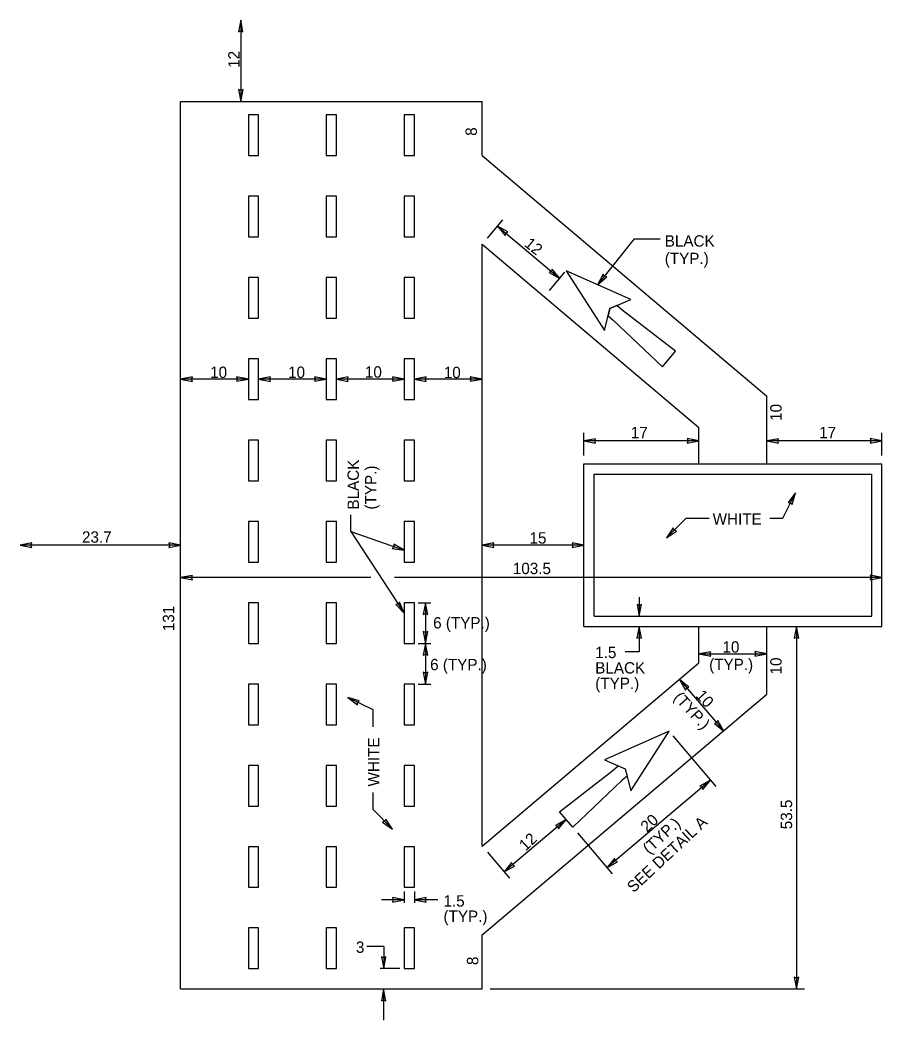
# Model space of a CAD drawing. Extents: x 319706 to 320019, y 1621790 to 1621976.
# Drawn here: x 319837.4 to 319943.4, y 1621853.1 to 1621976.1 of the extents above; entities that cross this region are included whole.
import ezdxf

# ---------------------------------------------------------------- set-up
doc = ezdxf.new("R2010")
doc.units = 0
for name, color, linetype in [('1', 7, 'Continuous'), ('40', 7, 'Continuous'), ('48', 7, 'Continuous'), ('52', 7, 'Continuous')]:
    doc.layers.add(name, color=color, linetype=linetype)

msp = doc.modelspace()

# ---------------------------------------------------------------- linework, layer by layer
at = {"layer": '1'}
for p, q in [((319857.17, 1621966.12), (319894.25, 1621966.12)), ((319857.17, 1621856.96), (319857.17, 1621966.12)), ((319894.25, 1621959.46), (319894.25, 1621966.12)), ((319894.25, 1621959.46), (319929.25, 1621929.87)), ((319894.25, 1621948.55), (319920.91, 1621926.01)), ((319894.25, 1621874.54), (319894.25, 1621948.55)), ((319929.25, 1621921.54), (319929.25, 1621929.87)), ((319920.91, 1621921.54), (319920.91, 1621926.01)), ((319906.75, 1621901.54), (319906.75, 1621921.54)), ((319906.75, 1621921.54), (319943.41, 1621921.54)), ((319943.41, 1621901.54), (319943.41, 1621921.54)), ((319908, 1621920.29), (319942.16, 1621920.29)), ((319908, 1621902.79), (319908, 1621920.29)), ((319942.16, 1621902.79), (319942.16, 1621920.29)), ((319908, 1621902.79), (319942.16, 1621902.79)), ((319906.75, 1621901.54), (319943.41, 1621901.54)), ((319920.91, 1621897.08), (319920.91, 1621901.54)), ((319929.25, 1621893.21), (319929.25, 1621901.54)), ((319894.25, 1621874.54), (319920.91, 1621897.08)), ((319894.25, 1621863.62), (319929.25, 1621893.21)), ((319894.25, 1621856.96), (319894.25, 1621863.62)), ((319857.17, 1621856.96), (319894.25, 1621856.96))]:
    msp.add_line(p, q, dxfattribs=at)
at = {"layer": '40'}
for p, q in [((319866.75, 1621964.46), (319865.5, 1621964.46)), ((319865.5, 1621964.46), (319865.5, 1621959.46)), ((319866.75, 1621959.46), (319866.75, 1621964.46)), ((319876.33, 1621964.46), (319875.08, 1621964.46)), ((319875.08, 1621964.46), (319875.08, 1621959.46)), ((319876.33, 1621959.46), (319876.33, 1621964.46)), ((319885.91, 1621964.46), (319884.66, 1621964.46)), ((319884.66, 1621964.46), (319884.66, 1621959.46)), ((319885.91, 1621959.46), (319885.91, 1621964.46)), ((319865.5, 1621959.46), (319866.75, 1621959.46)), ((319875.08, 1621959.46), (319876.33, 1621959.46)), ((319884.66, 1621959.46), (319885.91, 1621959.46)), ((319866.75, 1621954.46), (319865.5, 1621954.46)), ((319865.5, 1621954.46), (319865.5, 1621949.46)), ((319866.75, 1621949.46), (319866.75, 1621954.46)), ((319876.33, 1621954.46), (319875.08, 1621954.46)), ((319875.08, 1621954.46), (319875.08, 1621949.46)), ((319876.33, 1621949.46), (319876.33, 1621954.46)), ((319885.91, 1621954.46), (319884.66, 1621954.46)), ((319884.66, 1621954.46), (319884.66, 1621949.46)), ((319885.91, 1621949.46), (319885.91, 1621954.46)), ((319865.5, 1621949.46), (319866.75, 1621949.46)), ((319875.08, 1621949.46), (319876.33, 1621949.46)), ((319884.66, 1621949.46), (319885.91, 1621949.46)), ((319904.57, 1621945.27), (319909.27, 1621937.95)), ((319912.53, 1621941.75), (319904.57, 1621945.27)), ((319866.75, 1621944.46), (319865.5, 1621944.46)), ((319865.5, 1621944.46), (319865.5, 1621939.46)), ((319866.75, 1621939.46), (319866.75, 1621944.46)), ((319876.33, 1621944.46), (319875.08, 1621944.46)), ((319875.08, 1621944.46), (319875.08, 1621939.46)), ((319876.33, 1621939.46), (319876.33, 1621944.46)), ((319885.91, 1621944.46), (319884.66, 1621944.46)), ((319884.66, 1621944.46), (319884.66, 1621939.46)), ((319885.91, 1621939.46), (319885.91, 1621944.46)), ((319909.95, 1621940.66), (319912.53, 1621941.75)), ((319909.27, 1621937.95), (319909.95, 1621940.66)), ((319909.95, 1621940.66), (319909.73, 1621939.76)), ((319910.81, 1621941.03), (319909.95, 1621940.66)), ((319911.44, 1621940.48), (319910.81, 1621941.03)), ((319918.04, 1621935.38), (319911.44, 1621940.48)), ((319865.5, 1621939.46), (319866.75, 1621939.46)), ((319875.08, 1621939.46), (319876.33, 1621939.46)), ((319884.66, 1621939.46), (319885.91, 1621939.46)), ((319909.73, 1621939.76), (319910.36, 1621939.22)), ((319910.36, 1621939.22), (319916.41, 1621933.48)), ((319916.41, 1621933.48), (319918.04, 1621935.38)), ((319866.75, 1621934.46), (319865.5, 1621934.46)), ((319865.5, 1621934.46), (319865.5, 1621929.46)), ((319866.75, 1621929.46), (319866.75, 1621934.46)), ((319876.33, 1621934.46), (319875.08, 1621934.46)), ((319875.08, 1621934.46), (319875.08, 1621929.46)), ((319876.33, 1621929.46), (319876.33, 1621934.46)), ((319885.91, 1621934.46), (319884.66, 1621934.46)), ((319884.66, 1621934.46), (319884.66, 1621929.46)), ((319885.91, 1621929.46), (319885.91, 1621934.46)), ((319865.5, 1621929.46), (319866.75, 1621929.46)), ((319875.08, 1621929.46), (319876.33, 1621929.46)), ((319884.66, 1621929.46), (319885.91, 1621929.46)), ((319866.75, 1621924.46), (319865.5, 1621924.46)), ((319865.5, 1621924.46), (319865.5, 1621919.46)), ((319866.75, 1621919.46), (319866.75, 1621924.46)), ((319876.33, 1621924.46), (319875.08, 1621924.46)), ((319875.08, 1621924.46), (319875.08, 1621919.46)), ((319876.33, 1621919.46), (319876.33, 1621924.46)), ((319885.91, 1621924.46), (319884.66, 1621924.46)), ((319884.66, 1621924.46), (319884.66, 1621919.46)), ((319885.91, 1621919.46), (319885.91, 1621924.46)), ((319865.5, 1621919.46), (319866.75, 1621919.46)), ((319875.08, 1621919.46), (319876.33, 1621919.46)), ((319884.66, 1621919.46), (319885.91, 1621919.46)), ((319866.75, 1621914.46), (319865.5, 1621914.46)), ((319865.5, 1621914.46), (319865.5, 1621909.46)), ((319866.75, 1621909.46), (319866.75, 1621914.46)), ((319876.33, 1621914.46), (319875.08, 1621914.46)), ((319875.08, 1621914.46), (319875.08, 1621909.46)), ((319876.33, 1621909.46), (319876.33, 1621914.46)), ((319885.91, 1621914.46), (319884.66, 1621914.46)), ((319884.66, 1621914.46), (319884.66, 1621909.46)), ((319885.91, 1621909.46), (319885.91, 1621914.46)), ((319865.5, 1621909.46), (319866.75, 1621909.46)), ((319875.08, 1621909.46), (319876.33, 1621909.46)), ((319884.66, 1621909.46), (319885.91, 1621909.46)), ((319866.75, 1621904.46), (319865.5, 1621904.46)), ((319865.5, 1621904.46), (319865.5, 1621899.46)), ((319866.75, 1621899.46), (319866.75, 1621904.46)), ((319876.33, 1621904.46), (319875.08, 1621904.46)), ((319875.08, 1621904.46), (319875.08, 1621899.46)), ((319876.33, 1621899.46), (319876.33, 1621904.46)), ((319885.91, 1621904.46), (319884.66, 1621904.46)), ((319884.66, 1621904.46), (319884.66, 1621899.46)), ((319885.91, 1621899.46), (319885.91, 1621904.46)), ((319865.5, 1621899.46), (319866.75, 1621899.46)), ((319875.08, 1621899.46), (319876.33, 1621899.46)), ((319884.66, 1621899.46), (319885.91, 1621899.46)), ((319866.75, 1621894.46), (319865.5, 1621894.46)), ((319865.5, 1621894.46), (319865.5, 1621889.46)), ((319866.75, 1621889.46), (319866.75, 1621894.46)), ((319876.33, 1621894.46), (319875.08, 1621894.46)), ((319875.08, 1621894.46), (319875.08, 1621889.46)), ((319876.33, 1621889.46), (319876.33, 1621894.46)), ((319885.91, 1621894.46), (319884.66, 1621894.46)), ((319884.66, 1621894.46), (319884.66, 1621889.46)), ((319885.91, 1621889.46), (319885.91, 1621894.46)), ((319865.5, 1621889.46), (319866.75, 1621889.46)), ((319875.08, 1621889.46), (319876.33, 1621889.46)), ((319884.66, 1621889.46), (319885.91, 1621889.46)), ((319917.23, 1621888.66), (319909.27, 1621885.13)), ((319912.53, 1621881.33), (319917.23, 1621888.66)), ((319909.27, 1621885.13), (319911.85, 1621884.05)), ((319866.75, 1621884.46), (319865.5, 1621884.46)), ((319865.5, 1621884.46), (319865.5, 1621879.46)), ((319866.75, 1621879.46), (319866.75, 1621884.46)), ((319876.33, 1621884.46), (319875.08, 1621884.46)), ((319875.08, 1621884.46), (319875.08, 1621879.46)), ((319876.33, 1621879.46), (319876.33, 1621884.46)), ((319885.91, 1621884.46), (319884.66, 1621884.46)), ((319884.66, 1621884.46), (319884.66, 1621879.46)), ((319885.91, 1621879.46), (319885.91, 1621884.46)), ((319903.76, 1621878.76), (319910.36, 1621883.87)), ((319910.36, 1621883.87), (319910.99, 1621884.41)), ((319910.99, 1621884.41), (319911.85, 1621884.05)), ((319911.85, 1621884.05), (319912.08, 1621883.14)), ((319911.85, 1621884.05), (319912.53, 1621881.33)), ((319911.44, 1621882.6), (319905.39, 1621876.86)), ((319912.08, 1621883.14), (319911.44, 1621882.6)), ((319865.5, 1621879.46), (319866.75, 1621879.46)), ((319875.08, 1621879.46), (319876.33, 1621879.46)), ((319884.66, 1621879.46), (319885.91, 1621879.46)), ((319905.39, 1621876.86), (319903.76, 1621878.76)), ((319866.75, 1621874.46), (319865.5, 1621874.46)), ((319865.5, 1621874.46), (319865.5, 1621869.46)), ((319866.75, 1621869.46), (319866.75, 1621874.46)), ((319876.33, 1621874.46), (319875.08, 1621874.46)), ((319875.08, 1621874.46), (319875.08, 1621869.46)), ((319876.33, 1621869.46), (319876.33, 1621874.46)), ((319885.91, 1621874.46), (319884.66, 1621874.46)), ((319884.66, 1621874.46), (319884.66, 1621869.46)), ((319885.91, 1621869.46), (319885.91, 1621874.46)), ((319865.5, 1621869.46), (319866.75, 1621869.46)), ((319875.08, 1621869.46), (319876.33, 1621869.46)), ((319884.66, 1621869.46), (319885.91, 1621869.46)), ((319866.75, 1621864.46), (319865.5, 1621864.46)), ((319865.5, 1621864.46), (319865.5, 1621859.46)), ((319866.75, 1621859.46), (319866.75, 1621864.46)), ((319876.33, 1621864.46), (319875.08, 1621864.46)), ((319875.08, 1621864.46), (319875.08, 1621859.46)), ((319876.33, 1621859.46), (319876.33, 1621864.46)), ((319885.91, 1621864.46), (319884.66, 1621864.46)), ((319884.66, 1621864.46), (319884.66, 1621859.46)), ((319885.91, 1621859.46), (319885.91, 1621864.46)), ((319865.5, 1621859.46), (319866.75, 1621859.46)), ((319875.08, 1621859.46), (319876.33, 1621859.46)), ((319884.66, 1621859.46), (319885.91, 1621859.46))]:
    msp.add_line(p, q, dxfattribs=at)
at = {"layer": '48'}
for p, q in [((319864.56, 1621976.12), (319864.56, 1621966.12)), ((319894.89, 1621949.31), (319896.79, 1621951.55)), ((319896.14, 1621950.79), (319903.78, 1621944.34)), ((319912.93, 1621949.23), (319908.44, 1621943.56)), ((319912.93, 1621949.23), (319916.15, 1621949.23)), ((319902.53, 1621942.86), (319904.43, 1621945.1)), ((319865.5, 1621931.96), (319857.17, 1621931.96)), ((319875.08, 1621931.96), (319866.75, 1621931.96)), ((319884.66, 1621931.96), (319876.33, 1621931.96)), ((319894.25, 1621931.96), (319885.91, 1621931.96)), ((319906.75, 1621922.56), (319906.75, 1621925.36)), ((319920.91, 1621924.36), (319906.75, 1621924.36)), ((319943.41, 1621924.36), (319929.25, 1621924.36)), ((319943.41, 1621922.56), (319943.41, 1621925.36)), ((319931.22, 1621914.85), (319932.76, 1621917.96)), ((319878.08, 1621913.22), (319878.08, 1621915.29)), ((319919.32, 1621914.85), (319916.91, 1621912.46)), ((319919.32, 1621914.85), (319922.18, 1621914.85)), ((319929.61, 1621914.85), (319931.22, 1621914.85)), ((319878.08, 1621913.22), (319884.66, 1621910.92)), ((319878.08, 1621913.22), (319884.66, 1621903.17)), ((319857.17, 1621911.54), (319837.42, 1621911.54)), ((319906.75, 1621911.54), (319894.25, 1621911.54)), ((319880.55, 1621907.55), (319857.17, 1621907.55)), ((319943.41, 1621907.55), (319883.47, 1621907.55)), ((319886.37, 1621904.46), (319887.94, 1621904.46)), ((319887.28, 1621904.46), (319887.28, 1621899.46)), ((319913.56, 1621905.16), (319913.56, 1621902.79)), ((319913.56, 1621901.54), (319913.56, 1621898.43)), ((319932.9, 1621901.54), (319932.9, 1621856.96)), ((319886.37, 1621899.46), (319887.94, 1621899.46)), ((319887.28, 1621899.46), (319887.28, 1621894.46)), ((319913.56, 1621898.43), (319911.83, 1621898.43)), ((319920.91, 1621898.17), (319929.25, 1621898.17)), ((319918.53, 1621895), (319923.96, 1621888.67)), ((319886.37, 1621894.46), (319887.94, 1621894.46)), ((319880.84, 1621891.27), (319877.73, 1621892.81)), ((319880.84, 1621889.2), (319880.84, 1621891.27)), ((319917.69, 1621888.11), (319922.96, 1621881.88)), ((319922.31, 1621882.64), (319909.59, 1621871.87)), ((319880.84, 1621879.04), (319880.84, 1621881.12)), ((319880.84, 1621879.04), (319883.23, 1621876.63)), ((319904.57, 1621877.81), (319896.94, 1621871.35)), ((319905.97, 1621876.16), (319910.24, 1621871.11)), ((319894.89, 1621873.77), (319897.59, 1621870.58)), ((319884.66, 1621868.96), (319884.66, 1621867.54)), ((319885.91, 1621868.96), (319885.91, 1621867.54)), ((319884.66, 1621867.92), (319881.86, 1621867.92)), ((319888.79, 1621867.92), (319885.91, 1621867.92)), ((319882.14, 1621862.18), (319880.05, 1621862.18)), ((319882.14, 1621862.18), (319882.14, 1621859.46)), ((319884.12, 1621859.46), (319881.72, 1621859.46)), ((319882.13, 1621856.96), (319882.13, 1621853.14)), ((319895.25, 1621856.96), (319933.9, 1621856.96))]:
    msp.add_line(p, q, dxfattribs=at)
at = {"layer": '52'}
for p, q in [((319864.56, 1621976.12), (319864.28, 1621974.67)), ((319864.83, 1621974.67), (319864.56, 1621976.12)), ((319864.28, 1621974.67), (319864.56, 1621974.78)), ((319864.56, 1621974.78), (319864.83, 1621974.67)), ((319864.56, 1621967.46), (319864.29, 1621967.57)), ((319864.29, 1621967.57), (319864.56, 1621966.12)), ((319864.56, 1621966.12), (319864.84, 1621967.57)), ((319864.84, 1621967.57), (319864.56, 1621967.46)), ((319896.14, 1621950.79), (319897.06, 1621949.64)), ((319897.42, 1621950.06), (319896.14, 1621950.79)), ((319897.16, 1621949.92), (319897.42, 1621950.06)), ((319897.06, 1621949.64), (319897.16, 1621949.92)), ((319902.76, 1621945.21), (319902.5, 1621945.07)), ((319902.5, 1621945.07), (319903.78, 1621944.34)), ((319902.86, 1621945.49), (319902.76, 1621945.21)), ((319903.78, 1621944.34), (319902.86, 1621945.49)), ((319909.12, 1621944.86), (319908.44, 1621943.56)), ((319908.44, 1621943.56), (319909.56, 1621944.52)), ((319909.27, 1621944.61), (319909.12, 1621944.86)), ((319909.56, 1621944.52), (319909.27, 1621944.61)), ((319858.62, 1621932.23), (319857.17, 1621931.96)), ((319857.17, 1621931.96), (319858.62, 1621931.68)), ((319858.51, 1621931.96), (319858.62, 1621932.23)), ((319858.62, 1621931.68), (319858.51, 1621931.96)), ((319865.5, 1621931.96), (319864.05, 1621932.24)), ((319864.05, 1621932.24), (319864.16, 1621931.96)), ((319864.16, 1621931.96), (319864.05, 1621931.69)), ((319864.05, 1621931.69), (319865.5, 1621931.96)), ((319868.2, 1621932.23), (319866.75, 1621931.96)), ((319866.75, 1621931.96), (319868.2, 1621931.68)), ((319868.09, 1621931.96), (319868.2, 1621932.23)), ((319868.2, 1621931.68), (319868.09, 1621931.96)), ((319875.08, 1621931.96), (319873.63, 1621932.24)), ((319873.63, 1621932.24), (319873.74, 1621931.96)), ((319873.74, 1621931.96), (319873.63, 1621931.69)), ((319873.63, 1621931.69), (319875.08, 1621931.96)), ((319877.78, 1621932.23), (319876.33, 1621931.96)), ((319876.33, 1621931.96), (319877.78, 1621931.68)), ((319877.67, 1621931.96), (319877.78, 1621932.23)), ((319877.78, 1621931.68), (319877.67, 1621931.96)), ((319884.66, 1621931.96), (319883.21, 1621932.24)), ((319883.21, 1621932.24), (319883.32, 1621931.96)), ((319883.32, 1621931.96), (319883.21, 1621931.69)), ((319883.21, 1621931.69), (319884.66, 1621931.96)), ((319887.36, 1621932.23), (319885.91, 1621931.96)), ((319885.91, 1621931.96), (319887.36, 1621931.68)), ((319887.25, 1621931.96), (319887.36, 1621932.23)), ((319887.36, 1621931.68), (319887.25, 1621931.96)), ((319894.24, 1621931.96), (319892.79, 1621932.24)), ((319892.79, 1621932.24), (319892.9, 1621931.96)), ((319892.9, 1621931.96), (319892.79, 1621931.69)), ((319892.79, 1621931.69), (319894.24, 1621931.96)), ((319908.2, 1621924.63), (319906.75, 1621924.36)), ((319906.75, 1621924.36), (319908.2, 1621924.08)), ((319908.09, 1621924.36), (319908.2, 1621924.63)), ((319908.2, 1621924.08), (319908.09, 1621924.36)), ((319920.91, 1621924.36), (319919.46, 1621924.64)), ((319919.46, 1621924.64), (319919.57, 1621924.36)), ((319919.57, 1621924.36), (319919.46, 1621924.09)), ((319919.46, 1621924.09), (319920.91, 1621924.36)), ((319930.7, 1621924.63), (319929.25, 1621924.36)), ((319929.25, 1621924.36), (319930.7, 1621924.08)), ((319930.59, 1621924.36), (319930.7, 1621924.63)), ((319930.7, 1621924.08), (319930.59, 1621924.36)), ((319943.41, 1621924.36), (319941.96, 1621924.64)), ((319941.96, 1621924.64), (319942.07, 1621924.36)), ((319942.07, 1621924.36), (319941.96, 1621924.09)), ((319941.96, 1621924.09), (319943.41, 1621924.36)), ((319932.76, 1621917.96), (319931.86, 1621916.79)), ((319931.86, 1621916.79), (319932.16, 1621916.76)), ((319932.16, 1621916.76), (319932.36, 1621916.55)), ((319932.36, 1621916.55), (319932.76, 1621917.96)), ((319917.74, 1621913.67), (319916.9, 1621912.45)), ((319916.9, 1621912.45), (319918.13, 1621913.27)), ((319917.85, 1621913.4), (319917.74, 1621913.67)), ((319918.13, 1621913.27), (319917.85, 1621913.4)), ((319838.87, 1621911.81), (319837.42, 1621911.54)), ((319837.42, 1621911.54), (319838.87, 1621911.26)), ((319838.76, 1621911.54), (319838.87, 1621911.81)), ((319838.87, 1621911.26), (319838.76, 1621911.54)), ((319857.17, 1621911.54), (319855.72, 1621911.82)), ((319855.72, 1621911.82), (319855.83, 1621911.54)), ((319855.83, 1621911.54), (319855.72, 1621911.27)), ((319855.72, 1621911.27), (319857.17, 1621911.54)), ((319883.39, 1621911.36), (319883.2, 1621911.14)), ((319883.2, 1621911.14), (319884.66, 1621910.92)), ((319884.66, 1621910.92), (319883.38, 1621911.66)), ((319883.38, 1621911.66), (319883.39, 1621911.36)), ((319895.7, 1621911.81), (319894.25, 1621911.54)), ((319894.25, 1621911.54), (319895.7, 1621911.26)), ((319895.59, 1621911.54), (319895.7, 1621911.81)), ((319895.7, 1621911.26), (319895.59, 1621911.54)), ((319906.75, 1621911.54), (319905.3, 1621911.82)), ((319905.3, 1621911.82), (319905.41, 1621911.54)), ((319905.41, 1621911.54), (319905.3, 1621911.27)), ((319905.3, 1621911.27), (319906.75, 1621911.54)), ((319858.62, 1621907.82), (319857.17, 1621907.55)), ((319857.17, 1621907.55), (319858.62, 1621907.27)), ((319858.51, 1621907.55), (319858.62, 1621907.82)), ((319858.62, 1621907.27), (319858.51, 1621907.55)), ((319943.41, 1621907.55), (319941.96, 1621907.83)), ((319941.96, 1621907.83), (319942.07, 1621907.55)), ((319942.07, 1621907.55), (319941.96, 1621907.28)), ((319941.96, 1621907.28), (319943.41, 1621907.55)), ((319884.1, 1621904.54), (319883.93, 1621904.29)), ((319884.66, 1621903.17), (319884.1, 1621904.54)), ((319887.28, 1621904.46), (319887, 1621903.01)), ((319887.55, 1621903.01), (319887.28, 1621904.46)), ((319883.93, 1621904.29), (319883.64, 1621904.24)), ((319883.64, 1621904.24), (319884.66, 1621903.17)), ((319913.56, 1621904.13), (319913.29, 1621904.24)), ((319913.29, 1621904.24), (319913.56, 1621902.79)), ((319913.56, 1621902.79), (319913.84, 1621904.24)), ((319913.84, 1621904.24), (319913.56, 1621904.13)), ((319887, 1621903.01), (319887.28, 1621903.12)), ((319887.28, 1621903.12), (319887.55, 1621903.01)), ((319887.28, 1621900.8), (319887.01, 1621900.91)), ((319887.01, 1621900.91), (319887.28, 1621899.46)), ((319887.28, 1621899.46), (319887.56, 1621900.91)), ((319887.56, 1621900.91), (319887.28, 1621900.8)), ((319913.56, 1621901.54), (319913.28, 1621900.09)), ((319913.83, 1621900.09), (319913.56, 1621901.54)), ((319932.9, 1621901.54), (319932.62, 1621900.09)), ((319933.17, 1621900.09), (319932.9, 1621901.54)), ((319913.28, 1621900.09), (319913.56, 1621900.2)), ((319913.56, 1621900.2), (319913.83, 1621900.09)), ((319932.62, 1621900.09), (319932.9, 1621900.2)), ((319932.9, 1621900.2), (319933.17, 1621900.09)), ((319887.28, 1621899.46), (319887, 1621898.01)), ((319887.55, 1621898.01), (319887.28, 1621899.46)), ((319922.36, 1621898.44), (319920.91, 1621898.17)), ((319922.25, 1621898.17), (319922.36, 1621898.44)), ((319929.24, 1621898.17), (319927.79, 1621898.45)), ((319927.79, 1621898.45), (319927.9, 1621898.17)), ((319887, 1621898.01), (319887.28, 1621898.12)), ((319887.28, 1621898.12), (319887.55, 1621898.01)), ((319920.91, 1621898.17), (319922.36, 1621897.89)), ((319922.36, 1621897.89), (319922.25, 1621898.17)), ((319927.9, 1621898.17), (319927.79, 1621897.9)), ((319927.79, 1621897.9), (319929.24, 1621898.17)), ((319887.28, 1621895.8), (319887.01, 1621895.91)), ((319887.01, 1621895.91), (319887.28, 1621894.46)), ((319887.28, 1621894.46), (319887.56, 1621895.91)), ((319887.56, 1621895.91), (319887.28, 1621895.8)), ((319918.53, 1621895), (319919.26, 1621893.72)), ((319919.68, 1621894.08), (319918.53, 1621895)), ((319919.26, 1621893.72), (319919.4, 1621893.98)), ((319919.4, 1621893.98), (319919.68, 1621894.08)), ((319877.73, 1621892.81), (319878.9, 1621891.91)), ((319879.14, 1621892.41), (319877.73, 1621892.81)), ((319878.9, 1621891.91), (319878.93, 1621892.21)), ((319878.93, 1621892.21), (319879.14, 1621892.41)), ((319923.22, 1621889.96), (319923.08, 1621889.69)), ((319923.95, 1621888.67), (319923.22, 1621889.96)), ((319923.08, 1621889.69), (319922.8, 1621889.6)), ((319922.8, 1621889.6), (319923.95, 1621888.67)), ((319922.31, 1621882.64), (319921.03, 1621881.92)), ((319921.38, 1621881.5), (319922.31, 1621882.64)), ((319921.03, 1621881.92), (319921.29, 1621881.77)), ((319921.29, 1621881.77), (319921.38, 1621881.5)), ((319882.28, 1621877.58), (319882.01, 1621877.47)), ((319882.01, 1621877.47), (319883.23, 1621876.63)), ((319882.41, 1621877.86), (319882.28, 1621877.58)), ((319883.23, 1621876.63), (319882.41, 1621877.86)), ((319904.57, 1621877.81), (319903.28, 1621877.08)), ((319903.63, 1621876.66), (319904.57, 1621877.81)), ((319903.28, 1621877.08), (319903.54, 1621876.94)), ((319903.54, 1621876.94), (319903.63, 1621876.66)), ((319897.87, 1621872.5), (319896.94, 1621871.35)), ((319897.96, 1621872.22), (319897.87, 1621872.5)), ((319910.52, 1621873.01), (319909.59, 1621871.87)), ((319909.59, 1621871.87), (319910.87, 1621872.59)), ((319910.61, 1621872.73), (319910.52, 1621873.01)), ((319910.87, 1621872.59), (319910.61, 1621872.73)), ((319896.94, 1621871.35), (319898.22, 1621872.08)), ((319898.22, 1621872.08), (319897.96, 1621872.22)), ((319884.66, 1621867.92), (319883.21, 1621868.2)), ((319883.21, 1621868.2), (319883.32, 1621867.92)), ((319883.32, 1621867.92), (319883.21, 1621867.65)), ((319883.21, 1621867.65), (319884.66, 1621867.92)), ((319887.36, 1621868.19), (319885.91, 1621867.92)), ((319885.91, 1621867.92), (319887.36, 1621867.64)), ((319887.25, 1621867.92), (319887.36, 1621868.19)), ((319887.36, 1621867.64), (319887.25, 1621867.92)), ((319882.14, 1621860.8), (319881.87, 1621860.91)), ((319881.87, 1621860.91), (319882.14, 1621859.46)), ((319882.14, 1621859.46), (319882.42, 1621860.91)), ((319882.42, 1621860.91), (319882.14, 1621860.8)), ((319932.9, 1621858.3), (319932.63, 1621858.41)), ((319932.63, 1621858.41), (319932.9, 1621856.96)), ((319932.9, 1621856.96), (319933.18, 1621858.41)), ((319933.18, 1621858.41), (319932.9, 1621858.3)), ((319882.13, 1621856.96), (319881.85, 1621855.51)), ((319882.4, 1621855.51), (319882.13, 1621856.96)), ((319881.85, 1621855.51), (319882.13, 1621855.62)), ((319882.13, 1621855.62), (319882.4, 1621855.51))]:
    msp.add_line(p, q, dxfattribs=at)

# ---------------------------------------------------------------- texts
at = {"layer": '48'}
for s, rotation, p in [('12', 90, (319864.42, 1621970.24)), ('8', 90, (319893.6, 1621961.88)), ('12', 321.237, (319899.33, 1621948.4)), ('10', 90, (319931.07, 1621926.82)), ('BLACK', 90, (319879.09, 1621915.92)), ('(TYP.)', 90, (319881.24, 1621915.92)), ('131', 90, (319856.38, 1621900.96)), ('10', 90, (319931.07, 1621895.64)), ('(TYP.)', 312.4213, (319917.71, 1621892.73)), ('10', 312.4213, (319920.41, 1621892.97)), ('WHITE', 90, (319881.6, 1621881.86)), ('53.5', 90, (319932.36, 1621876.6)), ('SEE DETAIL A', 43.0352, (319912.86, 1621868.72)), ('20', 43.0352, (319914.52, 1621876.15)), ('(TYP.)', 43.0352, (319914.79, 1621873.46)), ('12', 43.0352, (319899.58, 1621873.85)), ('8', 90, (319893.77, 1621859.9))]:
    msp.add_text(s, height=1.4, rotation=rotation, dxfattribs=at).set_placement(p)
for s, p in [('BLACK', (319916.7, 1621948.25)), ('(TYP.)', (319916.7, 1621946.1)), ('10', (319860.8, 1621932.1)), ('10', (319870.38, 1621932.1)), ('10', (319879.83, 1621932.14)), ('10', (319889.53, 1621932.08)), ('17', (319912.53, 1621924.69)), ('17', (319935.68, 1621924.69)), ('WHITE', (319922.59, 1621914.06)), ('23.7', (319845.04, 1621911.84)), ('15', (319900.07, 1621911.73)), ('103.5', (319898.02, 1621907.98)), ('6 (TYP.)', (319888.22, 1621901.29)), ('10', (319923.8, 1621898.32)), ('1.5', (319908.15, 1621897.65)), ('6 (TYP.)', (319887.85, 1621896.16)), ('BLACK', (319908.15, 1621895.75)), ('(TYP.)', (319922.16, 1621896.17)), ('(TYP.)', (319908.15, 1621893.85)), ('1.5', (319889.49, 1621867.09)), ('(TYP.)', (319889.49, 1621865.21)), ('3', (319878.72, 1621861.4))]:
    msp.add_text(s, height=1.4, dxfattribs=at).set_placement(p)

doc.saveas('drawing.dxf')
